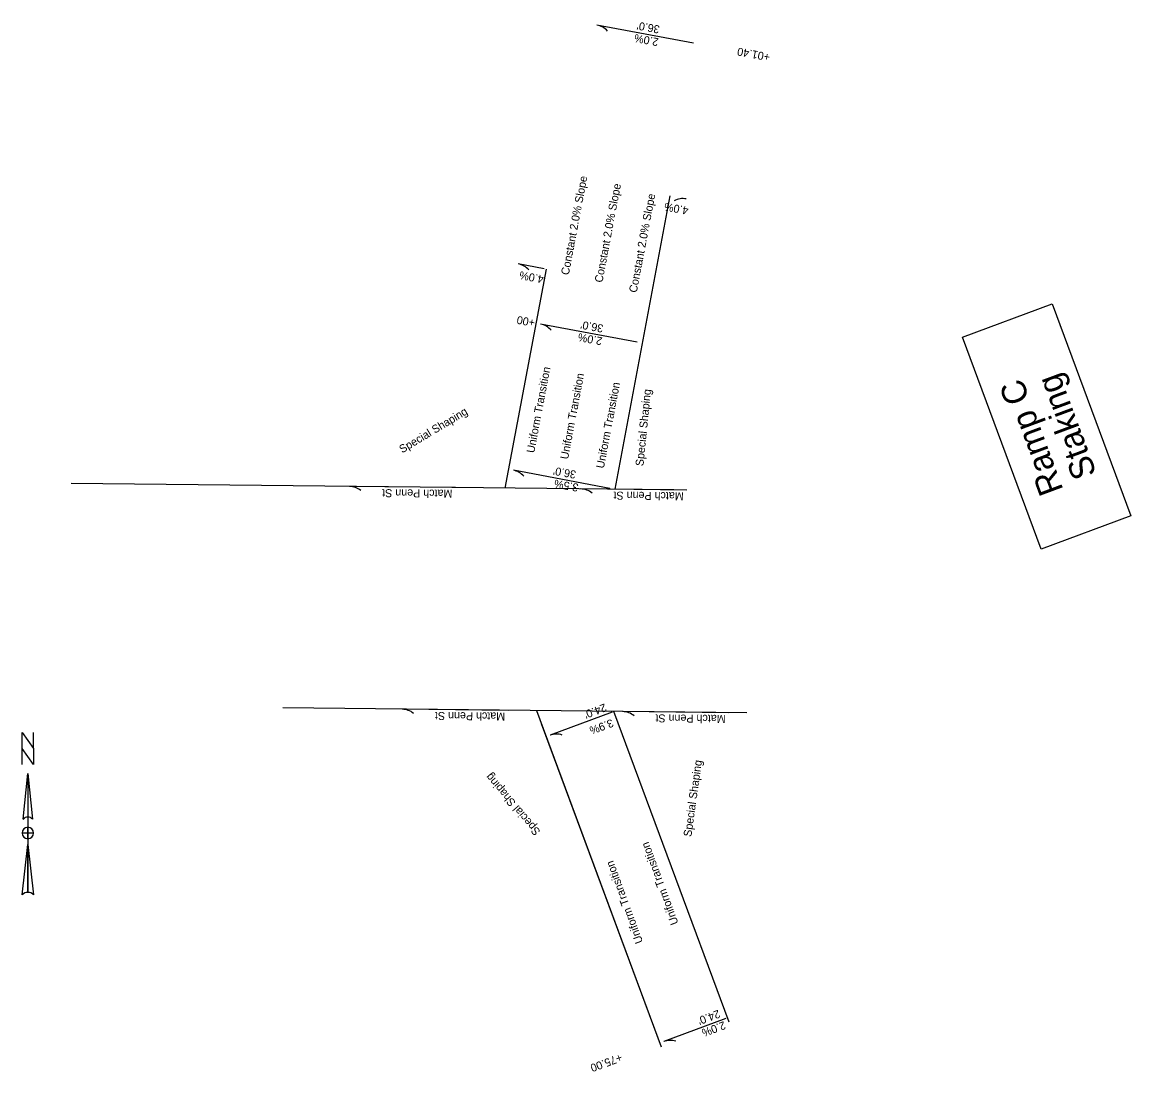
# Model space of a CAD drawing. Extents: x 20506035 to 20507470, y 7969245 to 7972296.
# Drawn here: x 20506034.7 to 20506403.8, y 7970414.4 to 7970763.9 of the extents above; entities that cross this region are included whole.
import ezdxf

# ---------------------------------------------------------------- set-up
doc = ezdxf.new("R2010")
doc.units = 0
for name, color, linetype in [('_CIVIL_CONSTRUCTION', 7, 'Continuous'), ('dsnStdLineWork', 7, 'Continuous'), ('EdgeShoulder', 7, 'Continuous'), ('Joints', 7, 'Continuous')]:
    doc.layers.add(name, color=color, linetype=linetype)

msp = doc.modelspace()

# ---------------------------------------------------------------- linework, layer by layer
at = {"layer": '_CIVIL_CONSTRUCTION'}
for p, q in [((20506258.23, 7970756.93), (20506226.05, 7970762.97)), ((20506208.49, 7970681.8), (20506199.87, 7970683.42)), ((20506239.47, 7970657.34), (20506207.3, 7970663.37)), ((20506230.39, 7970608.7), (20506198.22, 7970614.73)), ((20506178.97, 7970608.94), (20506143.61, 7970609.32)), ((20506256, 7970608.12), (20506220.64, 7970608.5)), ((20506196.56, 7970534.76), (20506161.19, 7970535.14)), ((20506231.12, 7970534.16), (20506210.44, 7970526.48)), ((20506269.96, 7970533.97), (20506234.6, 7970534.35)), ((20506268.96, 7970432.18), (20506248.28, 7970424.5))]:
    msp.add_line(p, q, dxfattribs=at)
for centre, start, end in [((20506224.91, 7970756.91), 41.1787, 79.3818), ((20506254.64, 7970699.01), 79.3818, 117.5848), ((20506198.73, 7970677.36), 41.1787, 79.3818), ((20506206.16, 7970657.31), 41.1787, 79.3818), ((20506197.08, 7970608.67), 41.1787, 79.3818), ((20506143.55, 7970603.16), 51.1864, 89.3894), ((20506220.58, 7970602.34), 51.1864, 89.3894), ((20506161.13, 7970528.98), 51.1864, 89.3894), ((20506234.54, 7970528.18), 51.1864, 89.3894), ((20506212.58, 7970520.7), 72.1535, 110.3566), ((20506250.42, 7970418.72), 72.1535, 110.3566)]:
    msp.add_arc(centre, 6.16, start, end, dxfattribs=at)
at = {"layer": 'dsnStdLineWork'}
for p, q in [((20506232.09, 7970608.38), (20506250.41, 7970706.08)), ((20506195.54, 7970608.77), (20506209.21, 7970681.67)), ((20506251.63, 7970608.17), (20506050.95, 7970610.31)), ((20506275.95, 7970533.9), (20506121.42, 7970535.57)), ((20506247.58, 7970422.65), (20506206.02, 7970534.66)), ((20506270.08, 7970430.99), (20506231.72, 7970534.38)), ((20506247.58, 7970422.65), (20506207.62, 7970530.34))]:
    msp.add_line(p, q, dxfattribs=at)
at = {"layer": 'EdgeShoulder'}
for p, q in [((20506036.56, 7970513.71), (20506038.09, 7970498.5)), ((20506036.56, 7970513.71), (20506036.56, 7970474.16)), ((20506035.04, 7970498.5), (20506035.04, 7970498.5)), ((20506035.1, 7970498.64), (20506035.39, 7970498.95)), ((20506036.56, 7970492.03), (20506036.56, 7970492.03)), ((20506034.66, 7970473.4), (20506036.56, 7970490.13))]:
    msp.add_line(p, q, dxfattribs=at)
msp.add_lwpolyline([(20506038.47, 7970516.75), (20506034.66, 7970522.07), (20506034.66, 7970527.4), (20506038.47, 7970522.07)], close=True, dxfattribs=at)
for points in [[(20506034.66, 7970516.75), (20506034.66, 7970527.4), (20506038.47, 7970522.07), (20506038.47, 7970527.4)], [(20506035.04, 7970498.5), (20506036.56, 7970513.71), (20506036.56, 7970499.26)], [(20506038.47, 7970493.93), (20506036.56, 7970493.93), (20506036.56, 7970495.83)], [(20506036.56, 7970492.03), (20506036.56, 7970493.93), (20506034.66, 7970493.93)], [(20506036.56, 7970474.16), (20506036.56, 7970490.13), (20506038.47, 7970473.4)]]:
    msp.add_lwpolyline(points, dxfattribs=at)
for centre, radius, start, end in [((20506036.56, 7970497.35), 1.9, 90.0204, 143.1257), ((20506036.56, 7970497.36), 1.9, 36.8481, 90.0218), ((20506036.56, 7970493.93), 1.9, 90, 180), ((20506036.56, 7970493.93), 1.9, 0, 90), ((20506036.56, 7970493.93), 1.9, 180, 270), ((20506036.56, 7970493.93), 1.9, 270, 360), ((20506036.56, 7970471.4), 2.76, 89.9894, 133.619), ((20506036.56, 7970471.4), 2.76, 46.4021, 90.0006)]:
    msp.add_arc(centre, radius, start, end, dxfattribs=at)
at = {"layer": 'Joints'}
for points in [[(20506377.62, 7970670.1), (20506403.82, 7970599.49), (20506374.01, 7970588.43), (20506347.81, 7970659.04)], [(20506374.01, 7970588.43), (20506347.81, 7970659.04), (20506377.62, 7970670.1), (20506403.82, 7970599.49)]]:
    msp.add_lwpolyline(points, close=True, dxfattribs=at)

# ---------------------------------------------------------------- texts
at = {"layer": '_CIVIL_CONSTRUCTION'}
for s, rotation, p in [("36.0'", 169.4845, (20506247.11, 7970762.71)), ('2.0%', 169.4845, (20506246.74, 7970758.5)), ('+01.40', 169.3818, (20506283.86, 7970753.48)), ('Constant 2.0% Slope', 79.271, (20506216.66, 7970679.56)), ('Constant 2.0% Slope', 79.271, (20506227.85, 7970677.05)), ('Constant 2.0% Slope', 79.271, (20506239.29, 7970673.69)), ('4.0%', 169.4845, (20506256.69, 7970702.37)), ('4.0%', 169.4845, (20506208.5, 7970679.53)), ('+00', 169.3305, (20506205.59, 7970665.04)), ("36.0'", 169.4845, (20506228.35, 7970663.12)), ('2.0%', 169.4845, (20506227.99, 7970658.91)), ('Uniform Transition', 79.271, (20506205.17, 7970620.31)), ('Uniform Transition', 79.271, (20506216.4, 7970618.19)), ('Uniform Transition', 79.271, (20506228.35, 7970615.18)), ('Special Shaping', 84.2577, (20506241.51, 7970616.01)), ('Special Shaping', 31.0212, (20506161.19, 7970620.31)), ("36.0'", 169.4845, (20506219.27, 7970614.48)), ('3.5%', 169.4845, (20506220.06, 7970610.16)), ('Match Penn St', 179.4921, (20506177.92, 7970608.22)), ('Match Penn St', 179.4921, (20506254.95, 7970607.4)), ("24.0'", 200.4593, (20506228.62, 7970537.11)), ('Match Penn St', 179.4921, (20506195.5, 7970534.04)), ('Match Penn St', 179.4921, (20506268.91, 7970533.24)), ('3.9%', 200.4593, (20506230.92, 7970531.97)), ('Special Shaping', 82.0254, (20506257.47, 7970492.57)), ('Special Shaping', 130.3699, (20506207.39, 7970494.5)), ('Uniform Transition', 110.1419, (20506253.22, 7970463.9)), ('Uniform Transition', 110.1419, (20506241.43, 7970457.66)), ("24.0'", 200.4593, (20506266.46, 7970435.13)), ('2.0%', 200.4593, (20506268.31, 7970431.33)), ('+75.00', 200.3566, (20506233.9, 7970420.59))]:
    msp.add_text(s, height=2.664, rotation=rotation, dxfattribs=at).set_placement(p)
at = {"layer": 'Joints'}
for s, p in [('Staking', (20506392.53, 7970613.52)), ('Ramp C', (20506381.45, 7970608.2))]:
    msp.add_text(s, height=8.16, rotation=110.3566, dxfattribs=at).set_placement(p)

doc.saveas('drawing.dxf')
